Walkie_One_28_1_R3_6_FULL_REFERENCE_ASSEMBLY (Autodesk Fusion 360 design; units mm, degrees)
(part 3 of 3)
sketch "Sketch14" plane through (0, 0, -22) normal (0, 0, 1) x axis (1, 0, 0)
  line L1 (26.9755, 27.0732) -> (16.9755, 27.0732)
  line L2 (26.9755, 19.0732) -> (26.9755, 27.0732)
  line L3 (16.9755, 19.0732) -> (26.9755, 19.0732)
  line L4 (16.9755, 27.0732) -> (16.9755, 19.0732)
  line L5 (-26.4387, -62.9268) -> (-16.9755, -62.9268)
  curve K1 (-20, -67) -> (-25.5105, -65.6599)
  line L6 (20, -67) -> (-20, -67)
  curve K2 (25.5105, -65.6599) -> (20, -67)
  curve K3 (32, -55) -> (30.6599, -60.5105)
  line L7 (32, 1.6132) -> (32, -55)
  line L8 (22.6952, 1.6132) -> (32, 1.6132)
  line L9 (22.6952, 5.6132) -> (22.6952, 1.6132)
  line L10 (32, 5.6132) -> (22.6952, 5.6132)
  line L11 (32, 55) -> (32, 5.6132)
  curve K4 (30.6599, 60.5105) -> (32, 55)
  line L12 (-20, 67) -> (20, 67)
  curve K5 (-25.5105, 65.6599) -> (-20, 67)
  line L13 (-32, -55) -> (-32, 55)
  curve K6 (-30.6599, -60.5105) -> (-32, -55)
  line L14 (-26.9755, -54.9268) -> (-26.9755, -62.2512)
  line L15 (-16.9755, -54.9268) -> (-26.9755, -54.9268)
  line L16 (-16.9755, -62.9268) -> (-16.9755, -54.9268)
  curve K7 (20, 67) -> (25.5105, 65.6599)
  curve K8 (-32, 55) -> (-30.6599, 60.5105)
  arc A1 centre (-31, -66) radius 5.5 clockwise from (-26.4387, -62.9268) to (-25.5105, -65.6599)
  arc A2 centre (31, -66) radius 5.5 clockwise from (25.5105, -65.6599) to (30.6599, -60.5105)
  arc A3 centre (31, 66) radius 5.5 clockwise from (30.6599, 60.5105) to (25.5105, 65.6599)
  arc A4 centre (-31, 66) radius 5.5 clockwise from (-25.5105, 65.6599) to (-30.6599, 60.5105)
  arc A5 centre (-31, -66) radius 5.5 clockwise from (-30.6599, -60.5105) to (-26.9755, -62.2512)
  circle C1 centre (-26, 28) radius 3.5
  circle C2 centre (26, 56) radius 3.5
  circle C3 centre (-25, 56) radius 3.5
  dimension "d391" diameter C1 = 7
  dimension "d392" diameter C2 = 7
  dimension "d393" diameter C3 = 7
extrude "Extrude15" add sketch "Sketch14" profile of C1 C2 C3 along normal blind 5.35
fillet "Fillet4" radius 1
position "Position10"
copy_paste "CutPaste"
sketch "Sketch23" plane through (0, 0, 0) normal (0, 0, 1) x axis (1, 0, 0)
  line L1 (32, 55) -> (32, -55)
  line L2 (-20, 67) -> (20, 67)
  line L3 (-32, -55) -> (-32, 55)
  line L4 (20, -67) -> (-20, -67)
  line L5 (-12.5, 62.5) -> (12.5, 62.5)
  line L6 (-24, 24) -> (-24, 51)
  line L7 (12.5, 12.5) -> (-12.5, 12.5)
  line L8 (24, 51) -> (24, 24)
  line L9 (12.5, 60.5) -> (-12.5, 60.5)
  line L10 (-22, 51) -> (-22, 24)
  line L11 (22, 24) -> (22, 51)
  line L12 (-12.5, 14.5) -> (12.5, 14.5)
  arc A1 centre (20, -55) radius 12 clockwise from (32, -55) to (20, -67)
  arc A2 centre (20, 55) radius 12 clockwise from (20, 67) to (32, 55)
  arc A3 centre (-20, 55) radius 12 clockwise from (-32, 55) to (-20, 67)
  arc A4 centre (-20, -55) radius 12 clockwise from (-20, -67) to (-32, -55)
  circle C1 centre (-0.0141, 38) radius 18
  circle C2 centre (0, 0) radius 2.4048
  circle C3 centre (0.0002, -18.0006) radius 1.3009
  circle C4 centre (0, -47) radius 15.55
  arc A5 centre (-12.5, 51) radius 11.5 clockwise from (-24, 51) to (-12.5, 62.5)
  arc A6 centre (-12.5, 24) radius 11.5 clockwise from (-12.5, 12.5) to (-24, 24)
  arc A7 centre (12.5, 24) radius 11.5 clockwise from (24, 24) to (12.5, 12.5)
  arc A8 centre (12.5, 51) radius 11.5 clockwise from (12.5, 62.5) to (24, 51)
  arc A9 centre (-12.5, 51) radius 9.5 clockwise from (-22, 51) to (-12.5, 60.5)
  arc A10 centre (12.5, 51) radius 9.5 clockwise from (12.5, 60.5) to (22, 51)
  arc A11 centre (12.5, 24) radius 9.5 clockwise from (22, 24) to (12.5, 14.5)
  arc A12 centre (-12.5, 24) radius 9.5 clockwise from (-12.5, 14.5) to (-22, 24)
extrude "Extrude23" new body of existing geometry blind -1 from offset -0.6
sketch "Sketch24" plane through (0, 0, 0.95) normal (0, 0, 1) x axis (1, 0, 0)
  line L1 (-22, 51) -> (-22, 24)
  line L2 (12.5, 60.5) -> (-12.5, 60.5)
  line L3 (22, 24) -> (22, 51)
  line L4 (-12.5, 14.5) -> (12.5, 14.5)
  line L5 (-12.5, 62.5) -> (12.5, 62.5)
  line L6 (-24, 24) -> (-24, 51)
  line L7 (12.5, 12.5) -> (-12.5, 12.5)
  line L8 (24, 51) -> (24, 24)
  arc A1 centre (-12.5, 24) radius 9.5 clockwise from (-12.5, 14.5) to (-22, 24)
  arc A2 centre (-12.5, 51) radius 9.5 clockwise from (-22, 51) to (-12.5, 60.5)
  arc A3 centre (12.5, 51) radius 9.5 clockwise from (12.5, 60.5) to (22, 51)
  arc A4 centre (12.5, 24) radius 9.5 clockwise from (22, 24) to (12.5, 14.5)
  arc A5 centre (-12.5, 51) radius 11.5 clockwise from (-24, 51) to (-12.5, 62.5)
  arc A6 centre (-12.5, 24) radius 11.5 clockwise from (-12.5, 12.5) to (-24, 24)
  arc A7 centre (12.5, 24) radius 11.5 clockwise from (24, 24) to (12.5, 12.5)
  arc A8 centre (12.5, 51) radius 11.5 clockwise from (12.5, 62.5) to (24, 51)
sketch "Sketch14" plane through (0, 0, 0.95) normal (0, 0, 1) x axis (1, 0, 0)
  line L1 (-22, 51) -> (-22, 24)
  line L2 (12.5, 60.5) -> (-12.5, 60.5)
  line L3 (22, 24) -> (22, 51)
  line L4 (-12.5, 14.5) -> (12.5, 14.5)
  line L5 (-12.5, 62.5) -> (12.5, 62.5)
  line L6 (-24, 24) -> (-24, 51)
  line L7 (12.5, 12.5) -> (-12.5, 12.5)
  line L8 (24, 51) -> (24, 24)
  line L9 (12.5, 12.5) -> (-12.5, 12.5)
  line L10 (-24, 24) -> (-24, 51)
  line L11 (-12.5, 62.5) -> (12.5, 62.5)
  line L12 (24, 51) -> (24, 24)
  line L13 (-21, 24) -> (-21, 51)
  line L14 (12.5, 15.5) -> (-12.5, 15.5)
  line L15 (21, 51) -> (21, 24)
  line L16 (-12.5, 59.5) -> (12.5, 59.5)
  arc A1 centre (-12.5, 24) radius 9.5 clockwise from (-12.5, 14.5) to (-22, 24)
  arc A2 centre (-12.5, 51) radius 9.5 clockwise from (-22, 51) to (-12.5, 60.5)
  arc A3 centre (12.5, 51) radius 9.5 clockwise from (12.5, 60.5) to (22, 51)
  arc A4 centre (12.5, 24) radius 9.5 clockwise from (22, 24) to (12.5, 14.5)
  arc A5 centre (-12.5, 51) radius 11.5 clockwise from (-24, 51) to (-12.5, 62.5)
  arc A6 centre (-12.5, 24) radius 11.5 clockwise from (-12.5, 12.5) to (-24, 24)
  arc A7 centre (12.5, 24) radius 11.5 clockwise from (24, 24) to (12.5, 12.5)
  arc A8 centre (12.5, 51) radius 11.5 clockwise from (12.5, 62.5) to (24, 51)
  arc A9 centre (12.5, 24) radius 11.5 clockwise from (24, 24) to (12.5, 12.5)
  arc A10 centre (-12.5, 24) radius 11.5 clockwise from (-12.5, 12.5) to (-24, 24)
  arc A11 centre (-12.5, 51) radius 11.5 clockwise from (-24, 51) to (-12.5, 62.5)
  arc A12 centre (12.5, 51) radius 11.5 clockwise from (12.5, 62.5) to (24, 51)
  arc A13 centre (-12.5, 24) radius 8.5 clockwise from (-12.5, 15.5) to (-21, 24)
  arc A14 centre (12.5, 24) radius 8.5 clockwise from (21, 24) to (12.5, 15.5)
  arc A15 centre (12.5, 51) radius 8.5 clockwise from (12.5, 59.5) to (21, 51)
  arc A16 centre (-12.5, 51) radius 8.5 clockwise from (-21, 51) to (-12.5, 59.5)
  dimension "d402" = -3
place_component sketch "Sketch14"
extrude "Extrude1" new body sketch "Sketch14" along normal blind 2
delete_face "DeleteFace2"
delete_face "DeleteFace3"
sketch "Sketch15" plane through (-40, 0, 0) normal (-1, 0, 0) x axis (0, 0, 1)
  line L1 (-13.1579, -20.1868) -> (-12, -20.1868)
  line L2 (-16, -19.497) -> (-16, -55)
  line L3 (-12, -55) -> (-16, -55)
  line L4 (-12, -20.1868) -> (-12, -55)
  line L5 (-16.6, -42.5) -> (-15.5, -49.6)
  line L6 (-10.55, -37.05) -> (-21.55, -37.05)
  line L7 (-10.55, -55.05) -> (-10.55, -37.05)
  line L8 (-21.55, -55.05) -> (-10.55, -55.05)
  line L9 (-21.55, -37.05) -> (-21.55, -55.05)
  line L10 (-10.55, -55.05) -> (-21.55, -37.05)
  line L11 (-21.55, -55.05) -> (-10.55, -37.05)
  arc A1 centre (-13.1579, -13.9868) radius 6.2 clockwise from (-13.1579, -20.1868) to (-16, -19.497)
  point P14 (-16.05, -46.05)
  point P12 (-10.55, -55.05)
  point P13 (-21.55, -55.05)
  point P11 (-10.55, -37.05)
  horizontal L6
  perpendicular L6 L7
  parallel L6 L8
  parallel L7 L9
  coincident L10 P14
  coincident L11 P14
  midpoint L5 P14
  dimension "d415" distance P12 P13 = 11
  dimension "d416" distance P11 P12 = 18
extrude "Extrude16" cut sketch "Sketch15" profile of L2 L3 L4 L6 L7 L8 L9 against normal blind 6
fillet "Fillet7" radius 3.5
fillet "Fillet5" radius 3.5
sketch "Sketch16" plane through (0, 0, -12) normal (0, 0, 1) x axis (1, 0, 0)
  line L1 (-42.1, 77.1) -> (42.1, 77.1)
  line L2 (-42.1, -77.1) -> (-42.1, 77.1)
  line L3 (42.1, -77.1) -> (-42.1, -77.1)
  line L4 (42.1, 77.1) -> (42.1, -77.1)
  line L5 (-42.1, -77.1) -> (42.1, 77.1)
  line L6 (42.1, -77.1) -> (-42.1, 77.1)
  point P6 (0, 0)
  point P1 (0, 0)
  point P4 (-42.1, -77.1)
  point P5 (42.1, -77.1)
  point P3 (-42.1, 77.1)
  horizontal L1
  perpendicular L1 L2
  parallel L1 L3
  parallel L2 L4
  coincident L5 P6
  coincident L6 P6
  coincident P1 P6
  dimension "d425" distance P4 P5 = 84.2 (= "80.2 mm + 4 mm")
  dimension "d426" distance P3 P4 = 154.2 (= "150.2 mm + 4 mm")
extrude "Extrude1" new body sketch "Sketch16" profile of L1 L2 L3 L4 distance 14
fillet "Fillet1" radius 22
fillet "Fillet2" radius 12
extrude "Extrude2" cut of existing geometry blind -40
shell "Shell2" innerThickness 2
sketch "Sketch17" plane through (-41.9, 0, 0) normal (-1, 0, 0) x axis (0, 0, 1)
  line L1 (-12.1, 34) -> (-11.9, 34)
  line L2 (-18, -14.1) -> (-18, 28.1)
  line L3 (-11.9, -20) -> (-12.1, -20)
  line L4 (-6, 28.1) -> (-6, -14.1)
  line L5 (-18.5, -14.1) -> (-18.5, 28.1)
  line L6 (-11.9, -20.5) -> (-12.1, -20.5)
  line L7 (-5.5, 28.1) -> (-5.5, -14.1)
  line L8 (-12.1, 34.5) -> (-11.9, 34.5)
  arc A1 centre (-11.9, 28.1) radius 5.9 clockwise from (-11.9, 34) to (-6, 28.1)
  arc A2 centre (-12.1, 28.1) radius 5.9 clockwise from (-18, 28.1) to (-12.1, 34)
  arc A3 centre (-12.1, -14.1) radius 5.9 clockwise from (-12.1, -20) to (-18, -14.1)
  arc A4 centre (-11.9, -14.1) radius 5.9 clockwise from (-6, -14.1) to (-11.9, -20)
  arc A5 centre (-12.1, 28.1) radius 6.4 clockwise from (-18.5, 28.1) to (-12.1, 34.5)
  arc A6 centre (-12.1, -14.1) radius 6.4 clockwise from (-12.1, -20.5) to (-18.5, -14.1)
  arc A7 centre (-11.9, -14.1) radius 6.4 clockwise from (-5.5, -14.1) to (-11.9, -20.5)
  arc A8 centre (-11.9, 28.1) radius 6.4 clockwise from (-11.9, 34.5) to (-5.5, 28.1)
  dimension "d437" = 0.5
extrude "Extrude3" cut sketch "Sketch17" against normal blind 9 and along normal blind 3
sketch "Sketch18" plane through (41, 0, 0) normal (1, 0, 0) x axis (0, 0, -1)
  line L1 (6.5, -15) -> (6.5, -7)
  line L2 (12.1, -20.4) -> (11.9, -20.4)
  line L3 (17.5, -7) -> (17.5, -15)
  line L4 (11.9, -1.6) -> (12.1, -1.6)
  line L5 (11.95, -14) -> (12.05, -14)
  line L6 (11.5, -8.45) -> (11.5, -13.55)
  line L7 (12.05, -8) -> (11.95, -8)
  line L8 (12.5, -13.55) -> (12.5, -8.45)
  line L9 (12.1, -20.9) -> (11.9, -20.9)
  line L10 (18, -7) -> (18, -15)
  line L11 (11.9, -1.1) -> (12.1, -1.1)
  line L12 (6, -15) -> (6, -7)
  arc A1 centre (11.9, -15) radius 5.4 clockwise from (11.9, -20.4) to (6.5, -15)
  arc A2 centre (12.1, -15) radius 5.4 clockwise from (17.5, -15) to (12.1, -20.4)
  arc A3 centre (12.1, -7) radius 5.4 clockwise from (12.1, -1.6) to (17.5, -7)
  arc A4 centre (11.9, -7) radius 5.4 clockwise from (6.5, -7) to (11.9, -1.6)
  arc A5 centre (11.95, -13.55) radius 0.45 clockwise from (11.95, -14) to (11.5, -13.55)
  arc A6 centre (11.95, -8.45) radius 0.45 clockwise from (11.5, -8.45) to (11.95, -8)
  arc A7 centre (12.05, -8.45) radius 0.45 clockwise from (12.05, -8) to (12.5, -8.45)
  arc A8 centre (12.05, -13.55) radius 0.45 clockwise from (12.5, -13.55) to (12.05, -14)
  arc A9 centre (11.9, -15) radius 5.9 clockwise from (11.9, -20.9) to (6, -15)
  arc A10 centre (12.1, -15) radius 5.9 clockwise from (18, -15) to (12.1, -20.9)
  arc A11 centre (12.1, -7) radius 5.9 clockwise from (12.1, -1.1) to (18, -7)
  arc A12 centre (11.9, -7) radius 5.9 clockwise from (6, -7) to (11.9, -1.1)
  dimension "d442" = 0.5
extrude "Extrude4" cut sketch "Sketch18" along normal blind 4 and against normal blind 16
sketch "Sketch19" plane through (41, 0, 0) normal (1, 0, 0) x axis (0, 0, -1)
  line L1 (6.5, 14) -> (6.5, 22)
  line L2 (12.1, 8.6) -> (11.9, 8.6)
  line L3 (17.5, 22) -> (17.5, 14)
  line L4 (11.9, 27.4) -> (12.1, 27.4)
  line L5 (9.45, 17.5) -> (11.5, 17.5)
  line L6 (9, 18.05) -> (9, 17.95)
  line L7 (11.5, 18.5) -> (9.45, 18.5)
  line L8 (11.5, 20.55) -> (11.5, 18.5)
  line L9 (12.05, 21) -> (11.95, 21)
  line L10 (12.5, 18.5) -> (12.5, 20.55)
  line L11 (14.55, 18.5) -> (12.5, 18.5)
  line L12 (15, 17.95) -> (15, 18.05)
  line L13 (12.5, 17.5) -> (14.55, 17.5)
  line L14 (12.5, 15.45) -> (12.5, 17.5)
  line L15 (11.95, 15) -> (12.05, 15)
  line L16 (11.5, 17.5) -> (11.5, 15.45)
  line L17 (12.1, 8.1) -> (11.9, 8.1)
  line L18 (18, 22) -> (18, 14)
  line L19 (11.9, 27.9) -> (12.1, 27.9)
  line L20 (6, 14) -> (6, 22)
  arc A1 centre (11.9, 14) radius 5.4 clockwise from (11.9, 8.6) to (6.5, 14)
  arc A2 centre (12.1, 14) radius 5.4 clockwise from (17.5, 14) to (12.1, 8.6)
  arc A3 centre (12.1, 22) radius 5.4 clockwise from (12.1, 27.4) to (17.5, 22)
  arc A4 centre (11.9, 22) radius 5.4 clockwise from (6.5, 22) to (11.9, 27.4)
  arc A5 centre (9.45, 17.95) radius 0.45 clockwise from (9.45, 17.5) to (9, 17.95)
  arc A6 centre (9.45, 18.05) radius 0.45 clockwise from (9, 18.05) to (9.45, 18.5)
  arc A7 centre (11.95, 20.55) radius 0.45 clockwise from (11.5, 20.55) to (11.95, 21)
  arc A8 centre (12.05, 20.55) radius 0.45 clockwise from (12.05, 21) to (12.5, 20.55)
  arc A9 centre (14.55, 18.05) radius 0.45 clockwise from (14.55, 18.5) to (15, 18.05)
  arc A10 centre (14.55, 17.95) radius 0.45 clockwise from (15, 17.95) to (14.55, 17.5)
  arc A11 centre (12.05, 15.45) radius 0.45 clockwise from (12.5, 15.45) to (12.05, 15)
  arc A12 centre (11.95, 15.45) radius 0.45 clockwise from (11.95, 15) to (11.5, 15.45)
  arc A13 centre (11.9, 14) radius 5.9 clockwise from (11.9, 8.1) to (6, 14)
  arc A14 centre (12.1, 14) radius 5.9 clockwise from (18, 14) to (12.1, 8.1)
  arc A15 centre (12.1, 22) radius 5.9 clockwise from (12.1, 27.9) to (18, 22)
  arc A16 centre (11.9, 22) radius 5.9 clockwise from (6, 22) to (11.9, 27.9)
  dimension "d447" = 0.5
extrude "Extrude5" cut sketch "Sketch19" along normal blind 7 and against normal blind 8
sketch "Sketch20" plane through (-42.1, 0, 0) normal (-1, 0, 0) x axis (0, 0, 1)
  line L1 (-14, -55.1) -> (-14, -20.2115)
  line L2 (-10, -55.1) -> (-14, -55.1)
  line L3 (-10, -20.2115) -> (-10, -55.1)
  line L4 (-12.1, -20.5) -> (-11.9, -20.5)
  line L5 (-12, -37.05) -> (-16, -37.05)
  curve K1 (-21.55, -40.55) -> (-18.05, -37.05)
  line L6 (-16, -37.05) -> (-18.05, -37.05)
  line L7 (-21.55, -40.55) -> (-21.55, -51.55)
  curve K2 (-18.6395, -55) -> (-21.55, -51.55)
  line L8 (-18.05, -55.05) -> (-16, -55.05)
  curve K3 (-18.6395, -55) -> (-18.05, -55.05)
  line L9 (-16, -55.05) -> (-12, -55.05)
  curve K4 (-12, -55.05) -> (-11.9325, -55)
  line L10 (-10.55, -52.2132) -> (-10.55, -39.8868)
  arc A1 centre (-12.1, -14.1) radius 6.4 clockwise from (-12.1, -20.5) to (-14, -20.2115)
  arc A2 centre (-11.9, -14.1) radius 6.4 clockwise from (-10, -20.2115) to (-11.9, -20.5)
  arc A3 centre (-14.05, -39.8868) radius 3.5 clockwise from (-12, -37.05) to (-10.55, -39.8868)
  arc A4 centre (-14.05, -52.2132) radius 3.5 clockwise from (-10.55, -52.2132) to (-11.9325, -55)
extrude "Extrude6" cut sketch "Sketch20" profile of L1 A3 L5 K1 L6 L7 K2 L8 K3 L9 A4 K4 L10 against normal blind 9 and along normal blind 5
fillet "Fillet3" radius 1.55
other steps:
extrude "Extrude2" cut sketch "Sketch12" against normal blind 6.5
extrude "Extrude14" cut sketch "Sketch6" against normal blind 6
extrude "Extrude25" cut sketch "Sketch15" profile of L2 L3 L4 L6 L7 L8 L9 against normal blind 6
create_component "CreateComponent3"
create_component "CreateComponent4"
create_component "CreateComponent6"
create_component "CreateComponent7"
create_component "CreateComponent9"
create_component "CreateComponent13"
create_component "CreateComponent14"
create_component "CreateComponent16"
create_component "CreateComponent17"
create_component "CreateComponent1"
create_component "CreateComponent2"
create_component "CreateComponent3"
create_component "CreateComponent4"
create_component "CreateComponent18"
create_component "CreateComponent1"
create_component "CreateComponent2"
create_component "CreateComponent3"
create_component "CreateComponent4"
create_component "CreateComponent5"
create_component "CreateComponent6"
create_component "CreateComponent7"
create_component "CreateComponent20"
create_component "CreateComponent21"
create_component "CreateComponent1"
create_component "CreateComponent1"
create_component "CreateComponent1"
create_component "CreateComponent2"
create_component "CreateComponent1"
create_component "CreateComponent3"
create_component "CreateComponent1"
create_component "CreateComponent4"
create_component "CreateComponent1"
create_component "CreateComponent5"
create_component "CreateComponent1"
create_component "CreateComponent6"
create_component "CreateComponent1"
create_component "CreateComponent7"
create_component "CreateComponent1"
create_component "CreateComponent8"
create_component "CreateComponent1"
create_component "CreateComponent9"
create_component "CreateComponent1"
create_component "CreateComponent10"
create_component "CreateComponent1"
create_component "CreateComponent11"
create_component "CreateComponent1"
create_component "CreateComponent1"
create_component "CreateComponent2"
create_component "CreateComponent12"
create_component "CreateComponent1"
create_component "CreateComponent13"
create_component "CreateComponent1"
create_component "CreateComponent14"
create_component "CreateComponent1"
create_component "CreateComponent1"
create_component "CreateComponent2"
create_component "CreateComponent15"
create_component "CreateComponent1"
create_component "CreateComponent16"
create_component "CreateComponent1"
create_component "CreateComponent1"
create_component "CreateComponent17"
create_component "CreateComponent1"
create_component "CreateComponent18"
create_component "CreateComponent1"
create_component "CreateComponent1"
create_component "CreateComponent2"
create_component "CreateComponent3"
create_component "CreateComponent4"
create_component "CreateComponent19"
create_component "CreateComponent1"
create_component "CreateComponent20"
create_component "CreateComponent1"
create_component "CreateComponent21"
create_component "CreateComponent1"
create_component "CreateComponent22"
create_component "CreateComponent22"
create_component "CreateComponent23"
create_component "CreateComponent24"
create_component "CreateComponent25" sketch "Sketch1"
create_component "CreateComponent26"
create_component "CreateComponent27"
create_component "CreateComponent28"
create_component "CreateComponent1"
create_component "CreateComponent1"
create_component "CreateComponent1"
create_component "CreateComponent1"
create_component "CreateComponent1"
create_component "CreateComponent2"
create_component "CreateComponent3"
create_component "CreateComponent4"
create_component "CreateComponent5"
create_component "CreateComponent6"
create_component "CreateComponent7"
create_component "CreateComponent8"
create_component "CreateComponent9"
create_component "CreateComponent10"
create_component "CreateComponent29"
create_component "CreateComponent30"
create_component "CreateComponent1"
create_component "CreateComponent2"
create_component "CreateComponent3"
create_component "CreateComponent4"
create_component "CreateComponent5"
create_component "CreateComponent6"
create_component "CreateComponent7"
create_component "CreateComponent8"
create_component "CreateComponent9"
create_component "CreateComponent10"
create_component "CreateComponent11"
create_component "CreateComponent12"
create_component "CreateComponent13"
create_component "CreateComponent14"
create_component "CreateComponent15"
create_component "CreateComponent16"
create_component "CreateComponent17"
create_component "CreateComponent18"
create_component "CreateComponent19"
create_component "CreateComponent20"
create_component "CreateComponent21"
create_component "CreateComponent22"
create_component "CreateComponent23"
create_component "CreateComponent24"
create_component "CreateComponent25"
create_component "CreateComponent26"
create_component "CreateComponent27"
create_component "CreateComponent28"
create_component "CreateComponent29"
create_component "CreateComponent30"
create_component "CreateComponent31"
create_component "CreateComponent32"
create_component "CreateComponent33"
create_component "CreateComponent31"
create_component "CreateComponent33"
create_component "CreateComponent34"
remove_body "RemoveBody1"
extrude "Extrude1" cut sketch "Sketch1" profile of A1 A2 L2 A3 A4 L4 L5 L6 A5 L7 A6 L8 L9 L10 L11 A7 L12 A8 L13 A9 L14 A10 L15 L17 along normal blind 6
extrude "Extrude1" cut sketch "Sketch1" profile of A1 A2 L2 A3 A4 L4 L5 L6 A5 L7 A6 L8 L9 L10 L11 A7 L12 A8 L13 A9 L14 A10 L15 L16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 along normal blind 9
create_component "CreateComponent35"
create_component "CreateComponent36"
remove_instance "RemoveInstance1"
create_component "CreateComponent37" sketch "Sketch14"
create_component "CreateComponent38"
named bodies: "C28_R2_Microphone_BOTTOM_PORT_Offset_Seal_REVIEW", "C28_R1_60_Black_Acoustic_Scrim", "Nominal U6 envelope - NOT SUPPLIER MODEL", "Adafruit board XY from Eagle - 0p8 thickness UNVERIFIED", "SPH0645 nominal envelope - bottom acoustic port - internal MEMS omitted", "C2 nominal passive envelope HEIGHT UNVERIFIED", "C4 nominal passive envelope HEIGHT UNVERIFIED", "R1 nominal passive envelope HEIGHT UNVERIFIED", "R2 nominal passive envelope HEIGHT UNVERIFIED", "C28_R3_REF_PTT_LIDUOLE_NOMINAL_6mm_NOT_OEM_1", "C28_R3_REF_PTT_LIDUOLE_NOMINAL_6mm_NOT_OEM_2", "C28_R3_REF_PTT_LIDUOLE_NOMINAL_6mm_NOT_OEM_3", "C28_R3_REF_PTT_LIDUOLE_NOMINAL_6mm_NOT_OEM_4", "C28_R3_REF_PTT_LIDUOLE_NOMINAL_6mm_NOT_OEM_5", "C28_R3_REF_PTT_LIDUOLE_NOMINAL_6mm_NOT_OEM_6", "C28_R3_REF_Volume_Up_LIDUOLE_NOMINAL_5mm_NOT_OEM_1", "C28_R3_REF_Volume_Up_LIDUOLE_NOMINAL_5mm_NOT_OEM_2", "C28_R3_REF_Volume_Up_LIDUOLE_NOMINAL_5mm_NOT_OEM_3", "C28_R3_REF_Volume_Up_LIDUOLE_NOMINAL_5mm_NOT_OEM_4", "C28_R3_REF_Volume_Up_LIDUOLE_NOMINAL_5mm_NOT_OEM_5", "C28_R3_REF_Volume_Up_LIDUOLE_NOMINAL_5mm_NOT_OEM_6", "C28_R3_REF_Volume_Down_LIDUOLE_NOMINAL_5mm_NOT_OEM_1", "C28_R3_REF_Volume_Down_LIDUOLE_NOMINAL_5mm_NOT_OEM_2", "C28_R3_REF_Volume_Down_LIDUOLE_NOMINAL_5mm_NOT_OEM_3", "C28_R3_REF_Volume_Down_LIDUOLE_NOMINAL_5mm_NOT_OEM_4", "C28_R3_REF_Volume_Down_LIDUOLE_NOMINAL_5mm_NOT_OEM_5", "C28_R3_REF_Volume_Down_LIDUOLE_NOMINAL_5mm_NOT_OEM_6", "C28_R3_REF_Front_LIDUOLE_NOMINAL_12x12x4p3_NOT_OEM_1", "C28_R3_REF_Front_LIDUOLE_NOMINAL_12x12x4p3_NOT_OEM_2", "C28_R3_REF_Front_LIDUOLE_NOMINAL_12x12x4p3_NOT_OEM_3", "C28_R3_REF_Front_LIDUOLE_NOMINAL_12x12x4p3_NOT_OEM_4", "C28_R3_REF_Front_LIDUOLE_NOMINAL_12x12x4p3_NOT_OEM_5", "C28_R3_REF_Front_LIDUOLE_NOMINAL_12x12x4p3_NOT_OEM_6", "C28_R3_4_F02_Flexible_Talk_Grip", "C28_R3_4_L01_Lens_Fit_Proxy", "C28_R3_4_L02_Light_Guide_Fit_Proxy", "C28_R3_6_P03_One_Piece_Play_Button", "C28_R3_6_P06_One_Piece_Volume_Up", "C28_R3_6_P07_One_Piece_Volume_Down", "C28_R3_4_L02_Light_Guide_Fit_Proxy (1)"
